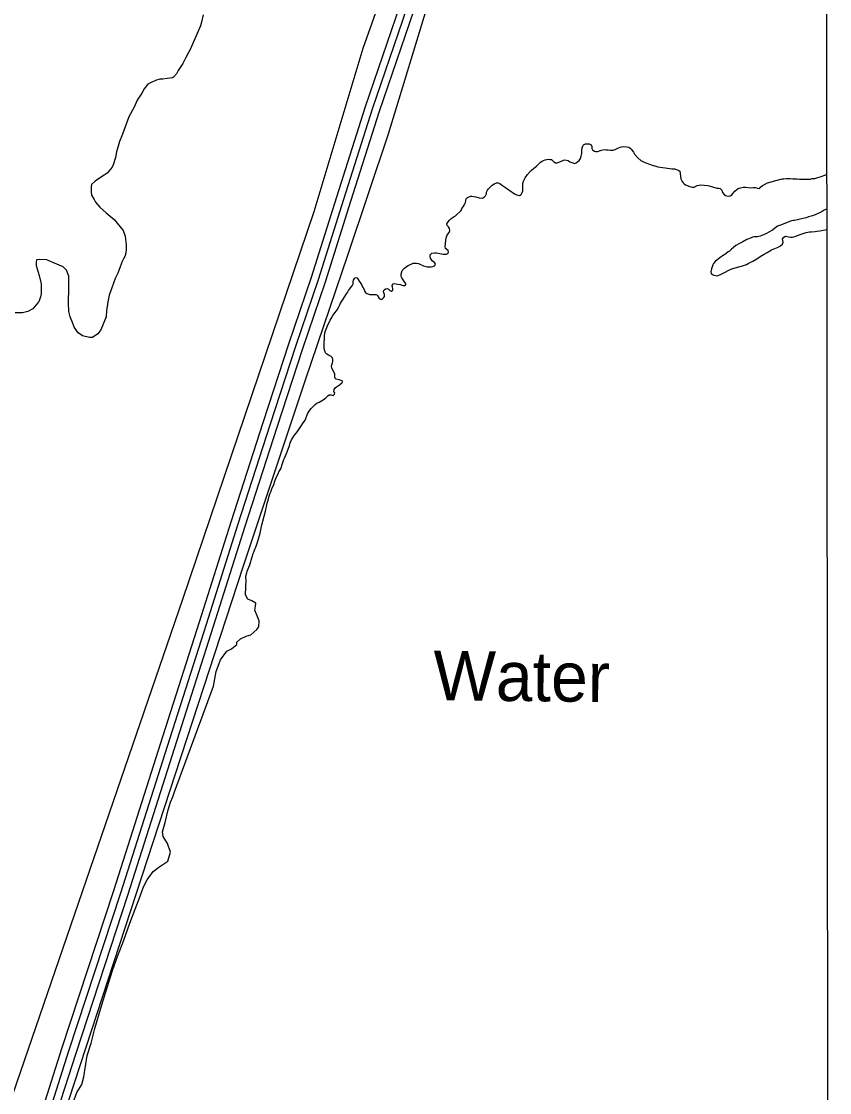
# Model space of a CAD drawing. Extents: x 3271442 to 3309282, y 752266 to 777610.
# Drawn here: x 3305424 to 3307057, y 763946 to 766109 of the extents above; entities that cross this region are included whole.
import ezdxf

# ---------------------------------------------------------------- set-up
doc = ezdxf.new("R2010")
doc.units = 0
for name, color, linetype in [('V-GRID-FRAM', 7, 'Continuous'), ('V-RIVR-IDEN', 7, 'Continuous'), ('V-ROAD-CNTR', 7, 'Continuous'), ('V-RTRN-LOCK-CHMB', 7, 'Continuous'), ('V-SITE-VEGE', 7, 'Continuous'), ('V-TOPO-SHOR', 7, 'Continuous')]:
    doc.layers.add(name, color=color, linetype=linetype)

msp = doc.modelspace()

# ---------------------------------------------------------------- linework, layer by layer
at = {"layer": 'V-GRID-FRAM'}
msp.add_lwpolyline([(3275591.3, 775827.4), (3307043.5, 775836.6), (3307056.7, 757650.8), (3275588.7, 757641.7), (3275591.3, 775827.4)], dxfattribs=at)
at = {"layer": 'V-ROAD-CNTR'}
for points in [[(3306247.2, 766310.9), (3306242, 766292.3), (3306197, 766167.8), (3306118.3, 765936.4), (3306060.1, 765754.2), (3306009.2, 765591.9), (3305963.2, 765457.5), (3305911.5, 765298.2), (3305846.5, 765098.1), (3305782.8, 764895.9), (3305709.2, 764666), (3305609.6, 764353.1), (3305504.8, 764033.8), (3305466.7, 763915), (3305447, 763850.1)], [(3306277.1, 766306.5), (3306270.6, 766283.2), (3306225.3, 766157.9), (3306146.8, 765927.1), (3306088.7, 765745.2), (3306037.7, 765582.5), (3305991.6, 765448), (3305940, 765289), (3305875.1, 765089), (3305811.3, 764886.8), (3305737.7, 764656.9), (3305638.1, 764343.9), (3305533.3, 764024.5), (3305495.3, 763906), (3305476.6, 763844.5)], [(3306211.2, 766162.8), (3306132.6, 765931.8), (3306074.4, 765749.7), (3306023.4, 765587.2), (3305977.4, 765452.7), (3305925.8, 765293.6), (3305860.8, 765093.6), (3305797.1, 764891.3), (3305723.4, 764661.5), (3305623.8, 764348.5), (3305519, 764029.1), (3305481, 763910.5)]]:
    msp.add_lwpolyline(points, dxfattribs=at)
at = {"layer": 'V-RTRN-LOCK-CHMB'}
for p, q in [((3306114.3, 766054.9), (3306219.2, 766352)), ((3306264.6, 766210.4), (3306164.8, 765881.8)), ((3306014.9, 765725.5), (3306114.3, 766054.9)), ((3306164.8, 765881.8), (3306083.4, 765638.1)), ((3305749.6, 764942.2), (3306014.9, 765725.5)), ((3306083.4, 765638.1), (3305996.7, 765384.5)), ((3305996.7, 765384.5), (3305871, 765007.1)), ((3305871, 765007.1), (3305474.6, 763794.1)), ((3305361.7, 763813), (3305749.6, 764942.2))]:
    msp.add_line(p, q, dxfattribs=at)
at = {"layer": 'V-SITE-VEGE'}
msp.add_lwpolyline([(3305791, 766122.5), (3305787.7, 766107.6), (3305785.2, 766100.1), (3305776.9, 766080.3), (3305771.1, 766067.9), (3305765.3, 766053.8), (3305761.1, 766046.3), (3305755.3, 766034.7), (3305749.5, 766024), (3305740.4, 766009.9), (3305737.1, 766003.3), (3305731.2, 765996.7), (3305728.8, 765995), (3305718, 765994.2), (3305709.7, 765992.6), (3305703.1, 765992.6), (3305694.8, 765990.1), (3305685.7, 765985.9), (3305679.1, 765982.6), (3305671.6, 765972.7), (3305666.6, 765964.4), (3305657.5, 765950.4), (3305651.7, 765936.3), (3305640.9, 765916.4), (3305635.9, 765904), (3305627.6, 765881.7), (3305621.8, 765866.8), (3305616, 765846.1), (3305613.5, 765834.5), (3305609.3, 765819.6), (3305606.8, 765814.6), (3305596.9, 765803), (3305591.1, 765798.9), (3305579.5, 765791.4), (3305572.8, 765786.5), (3305565.4, 765779.8), (3305564.5, 765774.9), (3305564.5, 765765.8), (3305565.4, 765758.3), (3305570.3, 765749.2), (3305573.6, 765744.2), (3305581.9, 765734.3), (3305595.1, 765722.7), (3305610.9, 765709.4), (3305629.1, 765687), (3305633.2, 765675.4), (3305635.6, 765658), (3305635.6, 765647.3), (3305633.1, 765635.7), (3305629.8, 765629.9), (3305627.3, 765624.1), (3305623.2, 765613.3), (3305618.2, 765600.9), (3305613.2, 765590.1), (3305606.6, 765571.1), (3305600.8, 765556.2), (3305598.3, 765542.9), (3305595.8, 765524.7), (3305594.9, 765512.3), (3305584.1, 765486.6), (3305578.3, 765478.4), (3305567.5, 765470.9), (3305560.9, 765470.9), (3305546.8, 765474.3), (3305538.6, 765480.1), (3305530.3, 765491.7), (3305527, 765500.8), (3305522, 765512.4), (3305519.6, 765523.2), (3305518.7, 765540.5), (3305518.8, 765551.3), (3305519.6, 765560.4), (3305519.6, 765594.4), (3305514.7, 765606.8), (3305508.1, 765613.4), (3305487.4, 765622.6), (3305474.9, 765627.6), (3305460, 765628.4), (3305454.2, 765627.6), (3305453.4, 765622.6), (3305453.4, 765616), (3305459.2, 765596.1), (3305463.3, 765579.5), (3305463.3, 765558.8), (3305462.4, 765553), (3305459.1, 765543.1), (3305456.6, 765540.6), (3305446.7, 765529), (3305436.7, 765523.2), (3305426, 765520.8), (3305411.1, 765520.8)], dxfattribs=at)
at = {"layer": 'V-TOPO-SHOR'}
for points in [[(3306532.1, 765825.9), (3306538.2, 765823.3), (3306541.6, 765822.3), (3306544.8, 765823.3), (3306548, 765826.1), (3306550.4, 765828.5), (3306553.2, 765832.5), (3306555, 765836.7), (3306555.8, 765842.3), (3306556.1, 765848.9), (3306556.9, 765853.7), (3306557.9, 765857.1), (3306559.7, 765859.7), (3306563.5, 765862.1), (3306567.9, 765862.1), (3306570.9, 765861.7), (3306574.8, 765859.6), (3306576, 765856.5), (3306576, 765852.7), (3306577.4, 765849.5), (3306581.4, 765846.9), (3306584.4, 765846.2), (3306588, 765846.4), (3306591.6, 765847.8), (3306595.6, 765849), (3306602, 765850.4), (3306605.2, 765850), (3306609, 765849.8), (3306613.8, 765849), (3306619.4, 765849.4), (3306623.2, 765850.6), (3306627.2, 765852.2), (3306630, 765853.6), (3306633.4, 765855), (3306636.4, 765856), (3306640.6, 765856.6), (3306647.2, 765856.2), (3306650.8, 765855.4), (3306653.4, 765853.4), (3306655.6, 765851), (3306660.4, 765845), (3306662.7, 765841.4), (3306669.3, 765833.4), (3306675.5, 765828.2), (3306682.3, 765824.8), (3306685.5, 765823.4), (3306699.9, 765818.2), (3306703.7, 765817.3), (3306709.7, 765815.7), (3306734.2, 765811.9), (3306738.2, 765811.5), (3306743, 765811.3), (3306747.2, 765810.3), (3306751, 765808.9), (3306753.8, 765806.7), (3306755, 765802.1), (3306755.2, 765796.3), (3306756, 765791.3), (3306758.8, 765786.1), (3306760.6, 765783.5), (3306763, 765781.3), (3306765.8, 765779.3), (3306774.4, 765775.9), (3306778.8, 765774.5), (3306783.2, 765774.5), (3306788.8, 765777.9), (3306793.4, 765778.7), (3306796.4, 765778.9), (3306810.1, 765777.9), (3306813.1, 765777.1), (3306822.3, 765774.1), (3306829.7, 765772.7), (3306832.9, 765772.3), (3306835.9, 765771.5), (3306838.7, 765768.7), (3306840.1, 765763.7), (3306843.5, 765759.3), (3306846.3, 765757.9), (3306851.5, 765756.1), (3306856.1, 765756.6), (3306858.9, 765758.8), (3306861.7, 765762.4), (3306865.3, 765766.2), (3306870.1, 765770.2), (3306873.5, 765772.6), (3306876.9, 765773.4), (3306882.1, 765774.2), (3306886.5, 765774.2), (3306898.5, 765773.4), (3306902.3, 765773.6), (3306906.5, 765773.6), (3306911.2, 765772.4), (3306914.8, 765771.8), (3306916.8, 765774.2), (3306921.2, 765777.6), (3306925, 765779.8), (3306931.2, 765782.9), (3306958, 765790.5), (3306961, 765791.1), (3306964.4, 765791.1), (3306969.8, 765791.7)], [(3306256.1, 765623.4), (3306253.9, 765625.6), (3306250.5, 765630.8), (3306249.5, 765635), (3306249.9, 765638), (3306253.1, 765640.8), (3306258.1, 765641.6), (3306262.3, 765641.8), (3306265.5, 765641.4), (3306272.5, 765639.6), (3306275.7, 765639.4), (3306279.3, 765639.4), (3306282.5, 765638.8), (3306285.3, 765640.2), (3306286.9, 765643.2), (3306285.9, 765646.4), (3306280.9, 765650.8), (3306280.1, 765654.9), (3306280.7, 765659.3), (3306281.3, 765667.9), (3306281.9, 765671.3), (3306283.5, 765675.9), (3306285.5, 765679.3), (3306288.1, 765683.1), (3306289.3, 765686.9), (3306288.9, 765690.9), (3306286.5, 765694.3), (3306283.7, 765697.1), (3306283.4, 765700.5), (3306285.8, 765704.1), (3306288.8, 765707.7), (3306292, 765710.9), (3306298, 765714.9), (3306300.8, 765716.5), (3306303.8, 765718.9), (3306309.8, 765724.9), (3306312, 765727.6), (3306313.6, 765731), (3306316, 765735), (3306319.8, 765740.6), (3306321, 765743.6), (3306321.4, 765747.4), (3306322.4, 765751), (3306325, 765753.4), (3306331, 765756), (3306334, 765756.2), (3306341.6, 765755), (3306348.5, 765753), (3306355.3, 765752.4), (3306359.1, 765754.6), (3306361.5, 765757.2), (3306363.3, 765761.2), (3306363.7, 765764.2), (3306365.1, 765768.2), (3306366.9, 765770.7), (3306372, 765775.9), (3306375, 765778.3), (3306380.1, 765781.7), (3306383.3, 765783.1), (3306386.7, 765783.3), (3306390.1, 765781.7), (3306395.9, 765777.7), (3306402.1, 765773.7), (3306413.5, 765765.5), (3306417.1, 765762.7), (3306420.1, 765760.7), (3306422.9, 765759.3), (3306426.7, 765758.1), (3306430.3, 765757.7), (3306433.5, 765759.9), (3306435.7, 765763.9), (3306436.7, 765766.9), (3306436.9, 765769.9), (3306436.9, 765773.9), (3306436.5, 765778.3), (3306436.9, 765782.1), (3306438.3, 765786.3), (3306439.9, 765790.3), (3306441.7, 765793.4), (3306446.3, 765799.8), (3306451.5, 765805.8), (3306453.7, 765808), (3306458.7, 765812.4), (3306461.5, 765814.8), (3306464.5, 765817), (3306472.7, 765824.8), (3306475.7, 765827), (3306478.3, 765828.6), (3306481.9, 765829.8), (3306488.5, 765830.8), (3306491.5, 765830.6), (3306494.5, 765830), (3306499.3, 765825.4), (3306503.1, 765823.4), (3306506.5, 765823.6), (3306511.9, 765825.5), (3306518.9, 765828.9), (3306521.9, 765829.7), (3306525.1, 765829.1), (3306528.7, 765828.1), (3306532.1, 765825.9)], [(3306969.8, 765791.7), (3306977.2, 765791.9), (3306982.2, 765791.5), (3306991, 765791.5), (3306995.8, 765790.9), (3307005.2, 765790.9), (3307011.8, 765790.4), (3307017.8, 765790.8), (3307021.6, 765791.6), (3307026.6, 765792.2), (3307033, 765793.8), (3307037.4, 765795.4), (3307041.7, 765796.4), (3307045.1, 765798), (3307050.8, 765799.7)], [(3307050.8, 765730.3), (3307045.9, 765727.9), (3307041.5, 765725.3), (3307036.5, 765722.7), (3307027.3, 765718.5), (3307022.3, 765716.7), (3307014.1, 765714.3), (3307009.3, 765712.5), (3306996.9, 765709.9), (3306991.7, 765708.5), (3306985.9, 765707.4), (3306982.9, 765707), (3306977.5, 765705.8), (3306959.3, 765698.4), (3306955.5, 765697), (3306951.7, 765695.4), (3306948.9, 765693.8), (3306941.3, 765687.6), (3306938.5, 765686.2), (3306928.9, 765680.6), (3306923.1, 765678.2), (3306916.3, 765675.7), (3306910.7, 765674.3), (3306907.7, 765674.1), (3306904.3, 765674.1), (3306900.9, 765673.3), (3306896.6, 765671.7)], [(3306896.6, 765671.7), (3306889.8, 765668.9), (3306881.2, 765664.3), (3306874.4, 765660.9), (3306867.4, 765656.7), (3306861.8, 765652.1), (3306858.8, 765649.1), (3306854.4, 765645.3), (3306851.8, 765643.6), (3306847.8, 765640.4), (3306844.8, 765638.6), (3306842, 765637.2), (3306834.6, 765632), (3306826.4, 765625), (3306822.2, 765620.2), (3306820.6, 765617.6), (3306818.2, 765609.2), (3306817, 765603.4), (3306817.5, 765600), (3306820.1, 765598.2), (3306822.9, 765597), (3306826.9, 765595.8), (3306830.5, 765595.6), (3306840.3, 765600), (3306844.5, 765602.4), (3306853.3, 765607), (3306858.9, 765609.2), (3306875.1, 765614), (3306878.9, 765614.8), (3306884.7, 765616.7), (3306888.5, 765618.3), (3306891.9, 765620.1), (3306896.3, 765622.1), (3306901.7, 765625.1), (3306909.5, 765629.9), (3306916.3, 765634.7), (3306924.3, 765639.3), (3306930.5, 765642.3), (3306939.5, 765647.7), (3306952.9, 765653.4), (3306957.7, 765656), (3306961.7, 765659.6), (3306963.1, 765663.2), (3306961.3, 765670), (3306964.1, 765673.4), (3306967.3, 765675.4), (3306970.7, 765675), (3306977.9, 765673.2), (3306981.9, 765673.6), (3306986.7, 765674.6), (3306997.3, 765679), (3307001.1, 765680.2), (3307005.1, 765681.2), (3307009.3, 765682.6), (3307016.1, 765684.1), (3307019.9, 765684.5), (3307027.4, 765684.9), (3307030.8, 765685.5), (3307037.2, 765686.3), (3307040.2, 765687.1), (3307050.9, 765688.6)], [(3306038.1, 765439.6), (3306036.5, 765444), (3306035.7, 765448), (3306035.3, 765451.8), (3306035.3, 765456.2), (3306035.5, 765460.2), (3306036.3, 765468.8), (3306036.3, 765473.6), (3306036.7, 765480.4), (3306038.1, 765484), (3306039.4, 765487.8), (3306042, 765494.2), (3306047.8, 765505.9), (3306049.6, 765509.1), (3306052.8, 765515.5), (3306055, 765518.1), (3306057.4, 765521.3), (3306059.6, 765523.7), (3306061.8, 765526.7), (3306064.6, 765531.7), (3306066.6, 765535.7), (3306068.4, 765539.9), (3306072.2, 765546.3), (3306080.2, 765558.9), (3306082.4, 765562), (3306084.4, 765565.4), (3306086.6, 765568.4), (3306091.4, 765574.2), (3306093.2, 765577), (3306093.8, 765580), (3306094, 765583.4), (3306094.8, 765586.6), (3306096.6, 765590), (3306098.8, 765592.2), (3306102, 765591.4), (3306104.4, 765588.2), (3306106.2, 765584.6), (3306111, 765577.8), (3306113.8, 765572), (3306115.4, 765569.4), (3306117.2, 765565.8), (3306118.2, 765562.6), (3306121.6, 765559.6), (3306127.9, 765557.8), (3306131.7, 765557.4), (3306139.5, 765557.4), (3306142.9, 765556), (3306144.3, 765553.2), (3306146.5, 765549.8), (3306149.5, 765548.4), (3306152.7, 765548), (3306155.3, 765551.2), (3306157.1, 765553.8), (3306157.1, 765557.8), (3306155.7, 765561), (3306155.5, 765564.2), (3306156.3, 765567.4), (3306159.3, 765569.4), (3306162.9, 765569.8), (3306165.7, 765568.6), (3306168.1, 765565.8), (3306171.1, 765564.5), (3306173.9, 765566.3), (3306174.3, 765569.7), (3306173.3, 765572.7), (3306173.1, 765576.1), (3306174.7, 765579.3), (3306177.9, 765579.7), (3306180.9, 765579.3), (3306183.9, 765578.5), (3306189.3, 765577.7), (3306192.1, 765576.5), (3306195.3, 765575.7), (3306198.9, 765575.7), (3306200.9, 765578.3), (3306199.1, 765581.5), (3306194.7, 765587.3), (3306192.5, 765591.1), (3306191.3, 765594.1), (3306190.9, 765598.7), (3306193.1, 765605.9), (3306197.9, 765610.9), (3306201.9, 765613.9), (3306204.9, 765615.9), (3306212.3, 765619.9), (3306215.1, 765621), (3306218.3, 765620.6), (3306221.7, 765621), (3306226.1, 765620.2), (3306229.9, 765618), (3306233.1, 765616.6), (3306236.3, 765615.4), (3306240.7, 765614.2), (3306243.7, 765613.8), (3306248.1, 765613.6), (3306251.7, 765613.8), (3306255.1, 765614.4), (3306258.1, 765615.6), (3306260.1, 765618.4), (3306259.1, 765621.6), (3306256.1, 765623.4)], [(3305887.3, 764870.1), (3305899.3, 764881.2), (3305903.6, 764886.4), (3305904, 764898.4), (3305901.6, 764905.1), (3305895.1, 764920.1), (3305896.3, 764928), (3305897.4, 764934.2), (3305889.2, 764939), (3305880.8, 764942), (3305876.7, 764951.1), (3305877.8, 764981.8), (3305877.2, 764985.6), (3305877.4, 764988.6), (3305878.8, 764995.8), (3305879.8, 764998.8), (3305885.2, 765011.6), (3305890.2, 765027.9), (3305892, 765034.3), (3305893.2, 765037.1), (3305894.4, 765041.1), (3305897.8, 765049.5), (3305901.4, 765059.7), (3305903.4, 765065.9), (3305906, 765075.7), (3305909.5, 765092.7), (3305910.5, 765096.7), (3305911.5, 765099.7), (3305914.1, 765109.6), (3305917.1, 765119.8), (3305918.9, 765129.4), (3305920.5, 765136), (3305921.3, 765140), (3305924.1, 765150.2), (3305925.7, 765154.8), (3305927.7, 765159), (3305929.9, 765165.2), (3305933.7, 765174.2), (3305935.9, 765180.8), (3305938.7, 765188.1), (3305942.5, 765195.7), (3305944.1, 765199.3), (3305947.7, 765205.5), (3305950.9, 765216.3), (3305954, 765224.1), (3305955, 765227.1), (3305959.4, 765236.7), (3305960.6, 765240.1), (3305963.6, 765247.5), (3305965, 765251.7), (3305966.2, 765256.1), (3305967.4, 765259.2), (3305969.6, 765264), (3305975.4, 765273.8), (3305981.4, 765281.2), (3305984.2, 765285), (3305989.4, 765292.8), (3305991.6, 765296.4), (3305996.8, 765303.6), (3305998.4, 765307), (3306002, 765316.8), (3306006.4, 765323.9), (3306009.2, 765327.3), (3306014.2, 765332.7), (3306017.2, 765335.5), (3306020.8, 765337.9), (3306025.2, 765340.5), (3306033.2, 765344.9), (3306036, 765346.9), (3306039.6, 765349.9), (3306042.6, 765352.7), (3306045.6, 765355.1), (3306049.6, 765354.7), (3306053.4, 765353.7), (3306056.2, 765356.3), (3306056.8, 765359.3), (3306055.2, 765361.9), (3306055.8, 765365.9), (3306057.8, 765369.1), (3306060.2, 765371), (3306066.6, 765375), (3306071.8, 765379.8), (3306073.4, 765382.4), (3306065.6, 765385), (3306059.6, 765386.6), (3306056.8, 765389), (3306056.8, 765396.6), (3306055.4, 765400.2), (3306052.1, 765406.2), (3306050.7, 765409.2), (3306050.3, 765412.4), (3306050.7, 765415.6), (3306052.1, 765419.4), (3306052.7, 765422.6), (3306053.1, 765426.6), (3306052.1, 765430), (3306049.7, 765432.2), (3306047.1, 765434), (3306043.9, 765435.2), (3306040.7, 765437), (3306038.1, 765439.6)], [(3305530.5, 763931), (3305535.5, 763945.9), (3305545.5, 763962), (3305549.6, 763977.4), (3305556.7, 764020.3), (3305564.3, 764045.8), (3305571.7, 764075.3), (3305584, 764116.2), (3305593.7, 764147.4), (3305607.9, 764192.2), (3305617.9, 764220.3), (3305630.4, 764253.7), (3305642.4, 764287.9), (3305653.3, 764316.4), (3305663.7, 764342.7), (3305670.2, 764361.6), (3305677.9, 764375.5), (3305689.7, 764392.4), (3305701.6, 764401.3), (3305719.4, 764413), (3305724.6, 764431.1), (3305719, 764449.1), (3305709.8, 764462.8), (3305708.4, 764472.2), (3305714, 764491.5), (3305720.4, 764516.7), (3305725, 764532.5), (3305729.9, 764543.4), (3305732.9, 764553.1), (3305811.6, 764766.3), (3305817.2, 764795.9), (3305825.7, 764820), (3305838.4, 764837.3), (3305848, 764842.3), (3305859, 764850.7), (3305859.2, 764855.2), (3305866.1, 764862.5), (3305877.9, 764867.4), (3305887.3, 764870.1)]]:
    msp.add_lwpolyline(points, dxfattribs=at)

# ---------------------------------------------------------------- texts
at = {"layer": 'V-RIVR-IDEN'}
msp.add_text('Water', height=100, rotation=359.4154, dxfattribs=at).set_placement((3306255.7, 764738.2))

doc.saveas('drawing.dxf')
